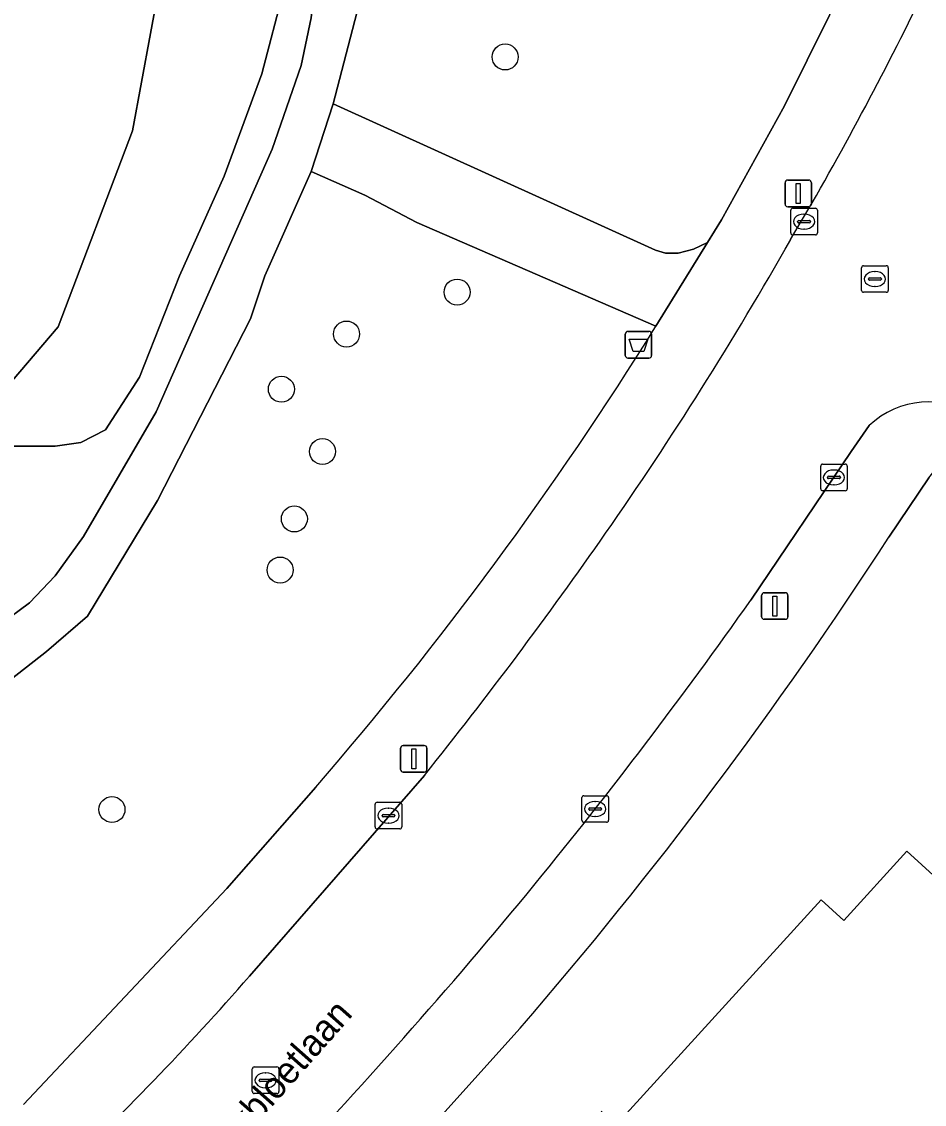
# Model space of a CAD drawing. Extents: x 161139 to 161601, y 381708 to 382245.
# Drawn here: x 161324.89 to 161358.84, y 382109.71 to 382150.42 of the extents above; entities that cross this region are included whole.
import ezdxf

# ---------------------------------------------------------------- set-up
doc = ezdxf.new("R2010")
doc.units = 0
for name, color, linetype in [('IMGEO_Afvalbak', 7, 'Continuous'), ('IMGEO_Boom', 7, 'Continuous'), ('IMGEO_Erf', 7, 'Continuous'), ('IMGEO_Groenvoorziening', 7, 'Continuous'), ('IMGEO_Kolk', 7, 'Continuous'), ('IMGEO_Lichtmast', 7, 'Continuous'), ('IMGEO_Oever', 7, 'Continuous'), ('IMGEO_Openbare_ruimte_label', 7, 'Continuous'), ('IMGEO_Pand', 7, 'Continuous'), ('IMGEO_Rijbaan_lokaal_open', 7, 'Continuous'), ('IMGEO_Rioolput', 7, 'Continuous'), ('IMGEO_Voetpad_halfverhard', 7, 'Continuous'), ('IMGEO_Voetpad_open', 7, 'Continuous'), ('IMGEO_Waterloop', 7, 'Continuous')]:
    doc.layers.add(name, color=color, linetype=linetype)

msp = doc.modelspace()

# ---------------------------------------------------------------- linework, layer by layer
at = {"layer": 'IMGEO_Afvalbak'}
for p, q in [((161347.592, 382137.871), (161347.592, 382138.671)), ((161347.592, 382138.671), (161347.592, 382137.871)), ((161347.692, 382138.771), (161348.482, 382138.771)), ((161348.482, 382138.771), (161347.692, 382138.771)), ((161348.582, 382138.671), (161348.582, 382137.871)), ((161348.582, 382137.871), (161348.582, 382138.671)), ((161348.482, 382137.771), (161347.692, 382137.771)), ((161347.692, 382137.771), (161348.482, 382137.771))]:
    msp.add_line(p, q, dxfattribs=at)
msp.add_lwpolyline([(161347.735, 382138.485), (161348.439, 382138.485), (161348.29, 382138.015), (161347.884, 382138.015), (161347.735, 382138.485)], dxfattribs=at)
for centre, start, end in [((161347.692, 382138.671), 90, 180), ((161347.692, 382138.671), 90, 180), ((161348.482, 382138.671), 0, 90), ((161348.482, 382138.671), 360, 90), ((161347.692, 382137.871), 180, 270), ((161347.692, 382137.871), 180, 270), ((161348.482, 382137.871), 270, 0), ((161348.482, 382137.871), 270, 0)]:
    msp.add_arc(centre, 0.1, start, end, dxfattribs=at)
at = {"layer": 'IMGEO_Boom'}
for centre in [(161343.072, 382149.092), (161341.266, 382140.251), (161337.108, 382138.674), (161334.657, 382136.597), (161336.202, 382134.255), (161335.144, 382131.721), (161334.608, 382129.8), (161328.284, 382120.794)]:
    msp.add_circle(centre, 0.489, dxfattribs=at)
at = {"layer": 'IMGEO_Erf'}
for points in [[(161359.011, 382133.266), (161357.507, 382131.037)], [(161346.685, 382109.457), (161347.252, 382108.941), (161354.956, 382117.404), (161355.81, 382116.625), (161358.18, 382119.228), (161364.817, 382113.186), (161354.661, 382102.03), (161356.521, 382100.336), (161355.647, 382099.376), (161364.97, 382090.887), (161358.81, 382084.121)], [(161343.639, 382112.574), (161336.623, 382104.782)]]:
    msp.add_lwpolyline(points, dxfattribs=at)
msp.add_arc((161216.665, 382222.387), 167.873, 319.14523, 327.03259, dxfattribs=at)
at = {"layer": 'IMGEO_Groenvoorziening'}
for points in [[(161359.507, 382201.57), (161353.731, 382186.932), (161344.615, 382184.315), (161337.542, 382185.06), (161337.959, 382181.16), (161338.168, 382180.035), (161338.395, 382177.758), (161338.395, 382166.358), (161338.529, 382160.641), (161338.381, 382157.382), (161338.055, 382153.747), (161337.775, 382152.581), (161337.659, 382151.388), (161336.609, 382147.324), (161348.733, 382141.824), (161349.1, 382141.708), (161349.584, 382141.717), (161350.164, 382141.864), (161350.687, 382142.115), (161351.211, 382142.964), (161353.579, 382147.259), (161356.983, 382154.109), (161361.896, 382165.076)], [(161324.059, 382127.738), (161325.185, 382128.568), (161326.152, 382129.58), (161327.219, 382131.065), (161329.947, 382135.744), (161334.304, 382145.623), (161335.401, 382148.776), (161335.772, 382150.565), (161335.917, 382151.909), (161336.138, 382153.065), (161336.484, 382158.418), (161336.701, 382164.913), (161336.527, 382172.023), (161336.255, 382180.214), (161336.009, 382181.571), (161335.966, 382181.993), (161335.873, 382184.733), (161335.816, 382190.191), (161336.152, 382191.491)], [(161333.68, 382191.476), (161333.916, 382188.563), (161334.723, 382182.759), (161335.628, 382178.803), (161335.937, 382170.785), (161335.506, 382160.426), (161334.764, 382151.677), (161333.924, 382148.46), (161332.502, 382144.61), (161330.82, 382140.866), (161329.321, 382137.046), (161328.04, 382135.077), (161327.111, 382134.597), (161326.145, 382134.454), (161324.604, 382134.454)], [(161348.743, 382138.968), (161339.754, 382142.864), (161337.8, 382143.893), (161335.783, 382144.791), (161334.039, 382140.859), (161333.492, 382139.245), (161329.991, 382132.416), (161327.363, 382128.067), (161325.827, 382126.739), (161320.668, 382122.71), (161318.534, 382121.746), (161316.868, 382120.679), (161313.667, 382119.221), (161311.526, 382118.511), (161307.792, 382117.551), (161305.011, 382117.06), (161302.655, 382116.812), (161298.499, 382116.75), (161296.247, 382116.835)], [(161324.958, 382109.709), (161332.601, 382117.82), (161335.947, 382121.635)]]:
    msp.add_lwpolyline(points, dxfattribs=at)
msp.add_arc((161232.712, 382211.238), 136.697, 319.04376, 328.08342, dxfattribs=at)
at = {"layer": 'IMGEO_Kolk'}
for p, q in [((161353.816, 382142.474), (161353.816, 382143.326)), ((161353.891, 382143.4), (161354.743, 382143.4)), ((161354.304, 382143.18), (161354.329, 382143.18)), ((161354.817, 382143.326), (161354.817, 382142.474)), ((161354.075, 382142.894), (161354.075, 382142.906)), ((161354.513, 382142.857), (161354.115, 382142.857)), ((161354.118, 382142.943), (161354.516, 382142.943)), ((161354.559, 382142.906), (161354.559, 382142.894)), ((161354.743, 382142.4), (161353.891, 382142.4)), ((161354.327, 382142.62), (161354.302, 382142.62)), ((161355.016, 382133.781), (161355.868, 382133.781)), ((161354.941, 382132.855), (161354.941, 382133.707)), ((161355.243, 382133.324), (161355.641, 382133.324)), ((161355.429, 382133.561), (161355.454, 382133.561)), ((161355.942, 382133.707), (161355.942, 382132.855)), ((161355.2, 382133.275), (161355.2, 382133.287)), ((161355.638, 382133.238), (161355.24, 382133.238)), ((161355.452, 382133.001), (161355.427, 382133.001)), ((161355.684, 382133.287), (161355.684, 382133.275)), ((161355.868, 382132.781), (161355.016, 382132.781)), ((161345.96, 382120.389), (161345.96, 382121.241)), ((161346.035, 382121.315), (161346.887, 382121.315)), ((161346.448, 382121.095), (161346.473, 382121.095)), ((161346.961, 382121.241), (161346.961, 382120.389)), ((161338.183, 382120.139), (161338.183, 382120.991)), ((161338.258, 382121.065), (161339.11, 382121.065)), ((161338.671, 382120.845), (161338.696, 382120.845)), ((161339.184, 382120.991), (161339.184, 382120.139)), ((161346.219, 382120.809), (161346.219, 382120.821)), ((161346.657, 382120.772), (161346.259, 382120.772)), ((161346.262, 382120.858), (161346.66, 382120.858)), ((161346.703, 382120.821), (161346.703, 382120.809)), ((161338.442, 382120.559), (161338.442, 382120.571)), ((161338.88, 382120.522), (161338.482, 382120.522)), ((161338.485, 382120.608), (161338.883, 382120.608)), ((161338.694, 382120.285), (161338.669, 382120.285)), ((161338.926, 382120.571), (161338.926, 382120.559)), ((161346.887, 382120.315), (161346.035, 382120.315)), ((161346.471, 382120.535), (161346.446, 382120.535)), ((161339.11, 382120.065), (161338.258, 382120.065))]:
    msp.add_line(p, q, dxfattribs=at)
for points in [[(161353.816, 382142.474), (161353.816, 382143.326)], [(161353.891, 382143.4), (161354.743, 382143.4)], [(161354.817, 382143.326), (161354.817, 382142.474)], [(161354.743, 382142.4), (161353.891, 382142.4)], [(161355.016, 382133.781), (161355.868, 382133.781)], [(161354.941, 382132.855), (161354.941, 382133.707)], [(161355.942, 382133.707), (161355.942, 382132.855)], [(161355.868, 382132.781), (161355.016, 382132.781)], [(161345.96, 382120.389), (161345.96, 382121.241)], [(161346.035, 382121.315), (161346.887, 382121.315)], [(161346.961, 382121.241), (161346.961, 382120.389)], [(161338.183, 382120.139), (161338.183, 382120.991)], [(161338.258, 382121.065), (161339.11, 382121.065)], [(161339.184, 382120.991), (161339.184, 382120.139)], [(161346.887, 382120.315), (161346.035, 382120.315)], [(161339.11, 382120.065), (161338.258, 382120.065)]]:
    msp.add_lwpolyline(points, dxfattribs=at)
for centre, radius, start, end in [((161353.893, 382143.324), 0.0765, 91.552, 178.448), ((161353.893, 382143.324), 0.0765, 91.552, 178.448), ((161354.741, 382143.324), 0.0765, 1.552, 88.448), ((161354.741, 382143.324), 0.0765, 1.552, 88.448), ((161354.115, 382142.903), 0.0403, 85.8775, 175.7526), ((161354.112, 382142.893), 0.0366, 178.938, 274.7102), ((161354.516, 382142.9), 0.043, 264.8664, 352.4533), ((161354.52, 382142.905), 0.0386, 1.7309, 96.639), ((161353.893, 382142.476), 0.0765, 181.552, 268.448), ((161353.893, 382142.476), 0.0765, 181.552, 268.448), ((161354.741, 382142.476), 0.0765, 271.552, 358.448), ((161354.741, 382142.476), 0.0765, 271.552, 358.448), ((161355.018, 382133.705), 0.0765, 91.552, 178.448), ((161355.018, 382133.705), 0.0765, 91.552, 178.448), ((161355.866, 382133.705), 0.0765, 1.552, 88.448), ((161355.866, 382133.705), 0.0765, 1.552, 88.448), ((161355.24, 382133.284), 0.0403, 85.8775, 175.7526), ((161355.645, 382133.286), 0.0386, 1.7309, 96.639), ((161355.237, 382133.274), 0.0366, 178.938, 274.7102), ((161355.641, 382133.281), 0.043, 264.8664, 352.4533), ((161355.018, 382132.857), 0.0765, 181.552, 268.448), ((161355.018, 382132.857), 0.0765, 181.552, 268.448), ((161355.866, 382132.857), 0.0765, 271.552, 358.448), ((161355.866, 382132.857), 0.0765, 271.552, 358.448), ((161346.037, 382121.239), 0.0765, 91.552, 178.448), ((161346.037, 382121.239), 0.0765, 91.552, 178.448), ((161346.885, 382121.239), 0.0765, 1.552, 88.448), ((161346.885, 382121.239), 0.0765, 1.552, 88.448), ((161338.26, 382120.989), 0.0765, 91.552, 178.448), ((161338.26, 382120.989), 0.0765, 91.552, 178.448), ((161339.108, 382120.989), 0.0765, 1.552, 88.448), ((161339.108, 382120.989), 0.0765, 1.552, 88.448), ((161346.259, 382120.818), 0.0403, 85.8775, 175.7526), ((161346.256, 382120.808), 0.0366, 178.938, 274.7102), ((161346.66, 382120.815), 0.043, 264.8664, 352.4533), ((161346.664, 382120.82), 0.0386, 1.7309, 96.639), ((161338.482, 382120.568), 0.0403, 85.8775, 175.7526), ((161338.479, 382120.558), 0.0366, 178.938, 274.7102), ((161338.883, 382120.565), 0.043, 264.8664, 352.4533), ((161338.887, 382120.57), 0.0386, 1.7309, 96.639), ((161346.037, 382120.391), 0.0765, 181.552, 268.448), ((161346.037, 382120.391), 0.0765, 181.552, 268.448), ((161346.885, 382120.391), 0.0765, 271.552, 358.448), ((161346.885, 382120.391), 0.0765, 271.552, 358.448), ((161338.26, 382120.141), 0.0765, 181.552, 268.448), ((161338.26, 382120.141), 0.0765, 181.552, 268.448), ((161339.108, 382120.141), 0.0765, 271.552, 358.448), ((161339.108, 382120.141), 0.0765, 271.552, 358.448)]:
    msp.add_arc(centre, radius, start, end, dxfattribs=at)
for centre, major_axis, ratio, start_param, end_param in [((161354.303, 382142.9), (-0.387, 0.002), 0.722429, 4.712389, 7.853982), ((161354.328, 382142.9), (-0.39, 0.002), 0.717154, 1.570796, 4.712389), ((161355.428, 382133.281), (-0.387, 0.002), 0.722429, 4.712389, 7.853982), ((161355.453, 382133.281), (-0.39, 0.002), 0.717154, 1.570796, 4.712389), ((161346.447, 382120.815), (-0.387, 0.002), 0.722429, 4.712389, 7.853982), ((161346.472, 382120.815), (-0.39, 0.002), 0.717154, 1.570796, 4.712389), ((161338.67, 382120.565), (-0.387, 0.002), 0.722429, 4.712389, 7.853982), ((161338.695, 382120.565), (-0.39, 0.002), 0.717154, 1.570796, 4.712389)]:
    msp.add_ellipse(centre, major_axis=major_axis, ratio=ratio, start_param=start_param, end_param=end_param, dxfattribs=at)
at = {"layer": 'IMGEO_Lichtmast'}
for p, q in [((161353.601, 382143.562), (161353.601, 382144.362)), ((161353.601, 382144.362), (161353.601, 382143.562)), ((161353.701, 382144.462), (161354.491, 382144.462)), ((161354.491, 382144.462), (161353.701, 382144.462)), ((161354.591, 382144.362), (161354.591, 382143.562)), ((161354.591, 382143.562), (161354.591, 382144.362)), ((161354.491, 382143.462), (161353.701, 382143.462)), ((161353.701, 382143.462), (161354.491, 382143.462)), ((161352.718, 382128.046), (161352.718, 382128.846)), ((161352.718, 382128.846), (161352.718, 382128.046)), ((161352.818, 382128.946), (161353.608, 382128.946)), ((161353.608, 382128.946), (161352.818, 382128.946)), ((161353.708, 382128.846), (161353.708, 382128.046)), ((161353.708, 382128.046), (161353.708, 382128.846)), ((161353.608, 382127.946), (161352.818, 382127.946)), ((161352.818, 382127.946), (161353.608, 382127.946)), ((161339.241, 382123.2), (161340.031, 382123.2)), ((161340.031, 382123.2), (161339.241, 382123.2)), ((161339.141, 382122.3), (161339.141, 382123.1)), ((161339.141, 382123.1), (161339.141, 382122.3)), ((161340.131, 382123.1), (161340.131, 382122.3)), ((161340.131, 382122.3), (161340.131, 382123.1)), ((161340.031, 382122.2), (161339.241, 382122.2)), ((161339.241, 382122.2), (161340.031, 382122.2))]:
    msp.add_line(p, q, dxfattribs=at)
for points in [[(161354.021, 382144.337), (161354.171, 382144.337), (161354.171, 382143.587), (161354.021, 382143.587), (161354.021, 382144.337)], [(161353.138, 382128.821), (161353.288, 382128.821), (161353.288, 382128.071), (161353.138, 382128.071), (161353.138, 382128.821)], [(161339.561, 382123.075), (161339.711, 382123.075), (161339.711, 382122.325), (161339.561, 382122.325), (161339.561, 382123.075)]]:
    msp.add_lwpolyline(points, dxfattribs=at)
for centre, start, end in [((161353.701, 382144.362), 90, 180), ((161353.701, 382144.362), 90, 180), ((161354.491, 382144.362), 0, 90), ((161354.491, 382144.362), 360, 90), ((161353.701, 382143.562), 180, 270), ((161353.701, 382143.562), 180, 270), ((161354.491, 382143.562), 270, 0), ((161354.491, 382143.562), 270, 0), ((161352.818, 382128.846), 90, 180), ((161352.818, 382128.846), 90, 180), ((161353.608, 382128.846), 0, 90), ((161353.608, 382128.846), 360, 90), ((161352.818, 382128.046), 180, 270), ((161352.818, 382128.046), 180, 270), ((161353.608, 382128.046), 270, 0), ((161353.608, 382128.046), 270, 0), ((161339.241, 382123.1), 90, 180), ((161339.241, 382123.1), 90, 180), ((161340.031, 382123.1), 0, 90), ((161340.031, 382123.1), 360, 90), ((161339.241, 382122.3), 180, 270), ((161339.241, 382122.3), 180, 270), ((161340.031, 382122.3), 270, 0), ((161340.031, 382122.3), 270, 0)]:
    msp.add_arc(centre, 0.1, start, end, dxfattribs=at)
at = {"layer": 'IMGEO_Oever'}
for points in [[(161327.749, 382192.066), (161327.749, 382179.446), (161328.12, 382177.407), (161328.455, 382174.35), (161329.006, 382166.381), (161329.381, 382163.294), (161329.381, 382161.758), (161330.118, 382158.687), (161330.118, 382155.961), (161330.078, 382155.228), (161330.078, 382151.821), (161329.062, 382146.314), (161326.26, 382138.94), (161319.905, 382131.505), (161315.156, 382127.793), (161310.013, 382125.411), (161303.499, 382123.707), (161291.8, 382122.732)], [(161324.604, 382134.454), (161326.145, 382134.454), (161327.111, 382134.597), (161328.04, 382135.077), (161329.321, 382137.046), (161330.82, 382140.866), (161332.502, 382144.61), (161333.924, 382148.46), (161334.764, 382151.677), (161335.506, 382160.426), (161335.937, 382170.785), (161335.628, 382178.803), (161334.723, 382182.759), (161333.916, 382188.563), (161333.68, 382191.476)]]:
    msp.add_lwpolyline(points, dxfattribs=at)
at = {"layer": 'IMGEO_Pand'}
msp.add_lwpolyline([(161338.619, 382100.588), (161339.157, 382100.098), (161331.456, 382091.639), (161332.405, 382090.775), (161329.934, 382088.061), (161336.5, 382082.084), (161346.729, 382093.319), (161348.62, 382091.598), (161349.515, 382092.582), (161358.81, 382084.121), (161364.97, 382090.887), (161355.647, 382099.376), (161356.521, 382100.336), (161354.661, 382102.03), (161364.817, 382113.186), (161358.18, 382119.228), (161355.81, 382116.625), (161354.956, 382117.404), (161347.252, 382108.941), (161346.685, 382109.457)], dxfattribs=at)
at = {"layer": 'IMGEO_Rijbaan_lokaal_open'}
for points in [[(161352.315, 382128.67), (161356.087, 382134.253), (161356.759, 382135.229)], [(161340.039, 382122.079), (161333.454, 382114.524)]]:
    msp.add_lwpolyline(points, dxfattribs=at)
for centre, radius, start, end in [((161243.727, 382207.375), 127.92, 329.38175, 333.96898), ((161230.202, 382212.434), 142.159, 325.14085, 330.40357), ((161358.998, 382132.863), 3.257, 55.7043, 133.4178), ((161203.791, 382231.164), 174.537, 321.31806, 325.051), ((161196.442, 382238.738), 190.818, 320.74581, 324.77255), ((161186.941, 382247.202), 203.531, 316.31175, 320.59327), ((161247.867, 382189.45), 113.75, 313.43897, 318.80017)]:
    msp.add_arc(centre, radius, start, end, dxfattribs=at)
at = {"layer": 'IMGEO_Rioolput'}
for p, q in [((161356.482, 382140.316), (161356.482, 382141.168)), ((161356.557, 382141.242), (161357.409, 382141.242)), ((161357.483, 382141.168), (161357.483, 382140.316)), ((161356.741, 382140.736), (161356.741, 382140.748)), ((161357.179, 382140.699), (161356.781, 382140.699)), ((161356.784, 382140.785), (161357.182, 382140.785)), ((161356.97, 382141.022), (161356.995, 382141.022)), ((161357.225, 382140.748), (161357.225, 382140.736)), ((161357.409, 382140.242), (161356.557, 382140.242)), ((161356.993, 382140.462), (161356.968, 382140.462)), ((161333.564, 382110.188), (161333.564, 382111.04)), ((161333.639, 382111.114), (161334.491, 382111.114)), ((161334.565, 382111.04), (161334.565, 382110.188)), ((161333.823, 382110.608), (161333.823, 382110.62)), ((161334.261, 382110.571), (161333.863, 382110.571)), ((161333.866, 382110.657), (161334.264, 382110.657)), ((161334.052, 382110.894), (161334.077, 382110.894)), ((161334.307, 382110.62), (161334.307, 382110.608)), ((161334.491, 382110.114), (161333.639, 382110.114)), ((161334.075, 382110.334), (161334.05, 382110.334))]:
    msp.add_line(p, q, dxfattribs=at)
for points in [[(161356.482, 382140.316), (161356.482, 382141.168)], [(161356.557, 382141.242), (161357.409, 382141.242)], [(161357.483, 382141.168), (161357.483, 382140.316)], [(161357.409, 382140.242), (161356.557, 382140.242)], [(161333.564, 382110.188), (161333.564, 382111.04)], [(161333.639, 382111.114), (161334.491, 382111.114)], [(161334.565, 382111.04), (161334.565, 382110.188)], [(161334.491, 382110.114), (161333.639, 382110.114)]]:
    msp.add_lwpolyline(points, dxfattribs=at)
for centre, radius, start, end in [((161356.559, 382141.166), 0.0765, 91.552, 178.448), ((161356.559, 382141.166), 0.0765, 91.552, 178.448), ((161357.407, 382141.166), 0.0765, 1.552, 88.448), ((161357.407, 382141.166), 0.0765, 1.552, 88.448), ((161356.781, 382140.745), 0.0403, 85.8775, 175.7526), ((161356.778, 382140.735), 0.0366, 178.938, 274.7102), ((161357.182, 382140.742), 0.043, 264.8664, 352.4533), ((161357.186, 382140.747), 0.0386, 1.7309, 96.639), ((161356.559, 382140.318), 0.0765, 181.552, 268.448), ((161356.559, 382140.318), 0.0765, 181.552, 268.448), ((161357.407, 382140.318), 0.0765, 271.552, 358.448), ((161357.407, 382140.318), 0.0765, 271.552, 358.448), ((161333.641, 382111.038), 0.0765, 91.552, 178.448), ((161333.641, 382111.038), 0.0765, 91.552, 178.448), ((161334.489, 382111.038), 0.0765, 1.552, 88.448), ((161334.489, 382111.038), 0.0765, 1.552, 88.448), ((161333.863, 382110.617), 0.0403, 85.8775, 175.7526), ((161333.86, 382110.607), 0.0366, 178.938, 274.7102), ((161334.264, 382110.614), 0.043, 264.8664, 352.4533), ((161334.268, 382110.619), 0.0386, 1.7309, 96.639), ((161333.641, 382110.19), 0.0765, 181.552, 268.448), ((161333.641, 382110.19), 0.0765, 181.552, 268.448), ((161334.489, 382110.19), 0.0765, 271.552, 358.448), ((161334.489, 382110.19), 0.0765, 271.552, 358.448)]:
    msp.add_arc(centre, radius, start, end, dxfattribs=at)
for centre, major_axis, ratio, start_param, end_param in [((161356.969, 382140.742), (-0.387, 0.002), 0.722429, 4.712389, 7.853982), ((161356.994, 382140.742), (-0.39, 0.002), 0.717154, 1.570796, 4.712389), ((161334.051, 382110.614), (-0.387, 0.002), 0.722429, 4.712389, 7.853982), ((161334.076, 382110.614), (-0.39, 0.002), 0.717154, 1.570796, 4.712389)]:
    msp.add_ellipse(centre, major_axis=major_axis, ratio=ratio, start_param=start_param, end_param=end_param, dxfattribs=at)
at = {"layer": 'IMGEO_Voetpad_halfverhard'}
for points in [[(161320.668, 382122.71), (161325.827, 382126.739), (161327.363, 382128.067), (161329.991, 382132.416), (161333.492, 382139.245), (161334.039, 382140.859), (161335.783, 382144.791), (161336.609, 382147.324), (161337.659, 382151.388), (161337.775, 382152.581), (161338.055, 382153.747), (161338.381, 382157.382), (161338.529, 382160.641), (161338.395, 382166.358), (161338.395, 382177.758), (161338.168, 382180.035), (161337.959, 382181.16), (161337.542, 382185.06), (161337.431, 382187.374), (161337.519, 382189.686), (161337.899, 382190.855), (161338.351, 382191.919)], [(161336.152, 382191.491), (161335.816, 382190.191), (161335.873, 382184.733), (161335.966, 382181.993), (161336.009, 382181.571), (161336.255, 382180.214), (161336.527, 382172.023), (161336.701, 382164.913), (161336.484, 382158.418), (161336.138, 382153.065), (161335.917, 382151.909), (161335.772, 382150.565), (161335.401, 382148.776), (161334.304, 382145.623), (161329.947, 382135.744), (161327.219, 382131.065), (161326.152, 382129.58), (161325.185, 382128.568), (161324.059, 382127.738)]]:
    msp.add_lwpolyline(points, dxfattribs=at)
msp.add_lwpolyline([(161336.609, 382147.324), (161335.783, 382144.791), (161337.8, 382143.893), (161339.754, 382142.864), (161348.743, 382138.968), (161350.687, 382142.115), (161350.164, 382141.864), (161349.584, 382141.717), (161349.1, 382141.708), (161348.733, 382141.824)], close=True, dxfattribs=at)
at = {"layer": 'IMGEO_Voetpad_open'}
for points in [[(161361.896, 382165.076), (161356.983, 382154.109), (161353.579, 382147.259), (161351.211, 382142.964), (161350.687, 382142.115), (161348.743, 382138.968)], [(161357.507, 382131.037), (161359.011, 382133.266), (161360.833, 382135.554)], [(161356.759, 382135.229), (161356.087, 382134.253), (161352.315, 382128.67)], [(161333.454, 382114.524), (161340.039, 382122.079)], [(161335.947, 382121.635), (161332.601, 382117.82), (161324.958, 382109.709)], [(161336.623, 382104.782), (161343.639, 382112.574)]]:
    msp.add_lwpolyline(points, dxfattribs=at)
for centre, radius, start, end in [((161243.727, 382207.375), 127.92, 329.38175, 333.96898), ((161230.202, 382212.434), 142.159, 325.14085, 330.40357), ((161232.712, 382211.238), 136.697, 319.04376, 328.08342), ((161358.998, 382132.863), 3.257, 55.7043, 133.4178), ((161203.791, 382231.164), 174.537, 321.31806, 325.051), ((161216.665, 382222.387), 167.873, 319.14523, 327.03259), ((161196.442, 382238.738), 190.818, 320.74581, 324.77255), ((161186.941, 382247.202), 203.531, 316.31175, 320.59327), ((161247.867, 382189.45), 113.75, 313.43897, 318.80017)]:
    msp.add_arc(centre, radius, start, end, dxfattribs=at)
at = {"layer": 'IMGEO_Waterloop'}
msp.add_lwpolyline([(161291.8, 382122.732), (161303.499, 382123.707), (161310.013, 382125.411), (161315.156, 382127.793), (161319.905, 382131.505), (161326.26, 382138.94), (161329.062, 382146.314), (161330.078, 382151.821), (161330.078, 382155.228), (161330.118, 382155.961), (161330.118, 382158.687), (161329.381, 382161.758), (161329.381, 382163.294), (161329.006, 382166.381), (161328.455, 382174.35), (161328.12, 382177.407), (161327.749, 382179.446), (161327.749, 382192.066)], dxfattribs=at)

# ---------------------------------------------------------------- texts
at = {"layer": 'IMGEO_Openbare_ruimte_label'}
msp.add_text('Jonckbloetlaan', height=1, rotation=48.4854, dxfattribs=at).set_placement((161331.465, 382106.401))

doc.saveas('drawing.dxf')
